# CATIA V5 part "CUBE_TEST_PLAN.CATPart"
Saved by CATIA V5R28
Part number: CUBE_TEST_PLAN
Bounding box of the stored display mesh (mm): x -25 to 25, y -25 to 25, z -25 to 25
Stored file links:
  C:\Users\remy.wolska\Desktop\CUBE_TEST_PLAN.CATPart
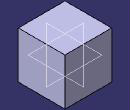
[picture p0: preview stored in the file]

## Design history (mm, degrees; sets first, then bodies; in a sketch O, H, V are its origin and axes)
Body1 (main body)
Body2 "CUBE_TEST_PLAN"
  Sketch1 on yz-plane, origin (0, 0, 0), H (0, 1, 0), V (0, 0, 1)
    point P1 (0, 0)
    line L1 (25, 25) -> (25, -25)
    line L2 (25, -25) -> (-25, -25)
    line L3 (-25, -25) -> (-25, 25)
    line L4 (-25, 25) -> (25, 25)
    reference intersected line E1 through (0, 0) direction (-1, 0) from xy-plane
    reference intersected line E2 through (0, 0) direction (0, 1) from zx-plane
    distance L4 L2 = 50
    distance L3 L1 = 50
    vertical: L1 V, L3 V
    horizontal: L2 H, L4 H
    equidistance: L1 L3 P1, L2 L4 P1
    coincidence: P1 E1, P1 E2
  Pad1: profile Sketch1, direction (1, 0, 0), length 25, mirrored extent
